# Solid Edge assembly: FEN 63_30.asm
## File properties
Title: Zylinder
Author: bmolnar
Template: iso assembly.asm
Last saved by: bmolnar
Revision: 14
Application: Solid Edge
Username: bmolnar
Dokumentum tartalom típus: 1
Document Number: FEN 63/30
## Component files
Kolbenstange.par
Profilrohr.par
Kit_1.par
Kit_2.par
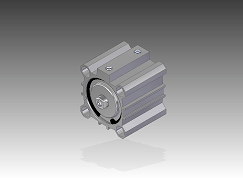
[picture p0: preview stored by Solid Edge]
